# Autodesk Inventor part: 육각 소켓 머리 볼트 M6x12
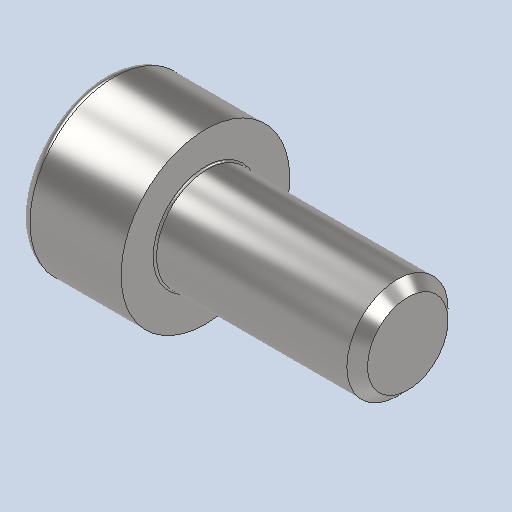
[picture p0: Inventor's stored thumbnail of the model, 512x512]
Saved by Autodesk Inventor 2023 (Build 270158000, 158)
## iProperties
Created: 2024-07
Part Number: 육각 소켓 머리 볼트 M6x12
Material: 강철, 연강
Description: 6각머리 태핑 나사
Document SubType Name: Modeling
Designer: home
Density: 7.85 g/cm^3
Appearance: 기본값
Author: jhkim
Sending System: Autodesk Inventor 2025
Preprocessor: ST-DEVELOPER v20
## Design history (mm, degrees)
feature "Solid1"
node "솔리드1"
